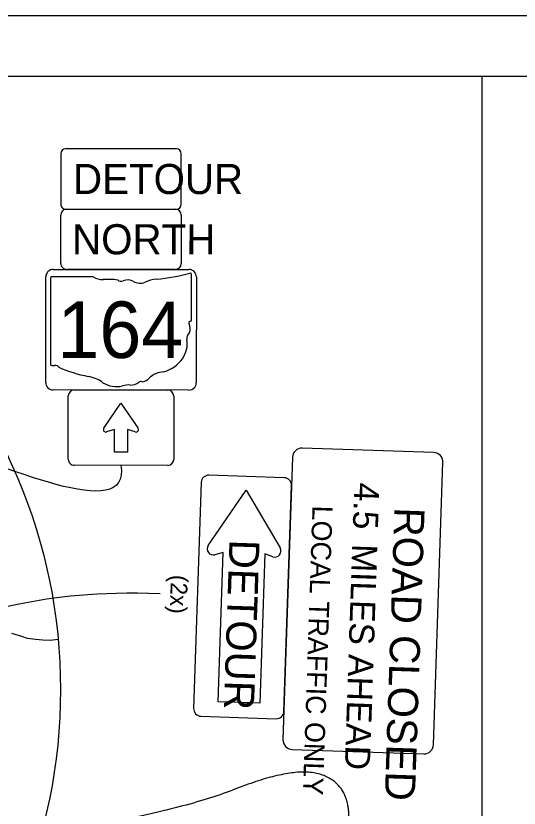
# Model space of a CAD drawing. Extents: x -202 to 1556, y 0 to 676.
# Drawn here: x 272.6 to 356.1, y 308.6 to 440 of the extents above; entities that cross this region are included whole.
import ezdxf

# ---------------------------------------------------------------- set-up
doc = ezdxf.new("R2010")
doc.units = 0
for name, color, linetype in [('Default', 7, 'Continuous'), ('GM_X_Minor_Lake', 7, 'Continuous'), ('GM_X_Minor_Lake_Text', 7, 'Continuous'), ('GM_X_Minor_River_Text', 7, 'Continuous'), ('SH_Border', 7, 'Continuous'), ('SH_Cut_Line', 7, 'Continuous'), ('SH_Data', 7, 'Continuous')]:
    doc.layers.add(name, color=color, linetype=linetype)

msp = doc.modelspace()

# ---------------------------------------------------------------- linework, layer by layer
at = {"layer": 'Default'}
msp.add_lwpolyline([(279.61, 336.58), (279.54, 336.57), (278.34, 336.4), (277.09, 336.41), (275.87, 336.52), (274.54, 336.72), (273.56, 337.02), (271.92, 337.55)], dxfattribs=at)
at = {"layer": 'GM_X_Minor_Lake'}
for p, q in [((281.05, 407.94), (299.05, 407.93)), ((280.05, 398.94), (280.05, 406.94)), ((300.05, 406.93), (300.05, 398.93)), ((299.05, 397.93), (281.05, 397.94)), ((301.76, 389.61), (301.77, 397.06)), ((278.33, 396.47), (278.32, 382.24)), ((285.42, 396.71), (278.56, 396.71)), ((301.76, 389.61), (301.76, 389.61)), ((282.29, 377.94), (297.79, 377.93)), ((281.29, 366.44), (281.29, 376.94)), ((298.79, 376.93), (298.79, 366.43)), ((287.2, 371.61), (290.04, 375.75)), ((290.04, 375.75), (292.84, 371.67)), ((288.95, 371.37), (287.66, 370.97)), ((288.94, 367.62), (288.95, 371.37)), ((292.42, 370.97), (291.13, 371.37)), ((291.13, 371.37), (291.13, 367.62)), ((291.13, 367.62), (288.94, 367.62)), ((297.79, 365.43), (282.29, 365.44)), ((304.52, 352.13), (310.81, 361.3)), ((310.81, 361.3), (316.46, 351.73)), ((307.02, 351), (305.62, 350.61)), ((306.19, 326.23), (307.02, 351)), ((313.89, 350.77), (313.06, 326)), ((315.26, 350.28), (313.89, 350.77)), ((313.06, 326), (306.19, 326.23))]:
    msp.add_line(p, q, dxfattribs=at)
for points in [[(280.05, 417.14), (280.05, 408.74)], [(299.25, 417.93), (280.85, 417.94)], [(300.05, 408.73), (300.05, 417.13)], [(280.85, 407.94), (299.25, 407.93)], [(278.8, 397.94), (301.3, 397.93)], [(277.54, 379.19), (277.55, 396.69)], [(302.55, 396.68), (302.54, 379.18)], [(301.29, 377.93), (278.79, 377.94)], [(317.13, 363.38), (304.64, 363.8)], [(303.35, 362.59), (302.09, 325.11)], [(317.08, 324.61), (318.34, 362.09)], [(303.3, 323.82), (315.79, 323.4)]]:
    msp.add_lwpolyline(points, dxfattribs=at)
for centre, radius, start, end in [((280.85, 417.14), 0.8, 89.9827, 179.9827), ((299.25, 417.13), 0.8, 359.9827, 89.9827), ((280.85, 408.74), 0.8, 179.9827, 269.9827), ((281.05, 406.94), 1, 89.9827, 179.9827), ((299.05, 406.93), 1, 359.9827, 89.9827), ((299.25, 408.73), 0.8, 269.9827, 359.9827), ((281.05, 398.94), 1, 179.9827, 269.9827), ((299.05, 398.93), 1, 269.9827, 359.9827), ((278.8, 396.69), 1.25, 89.9827, 179.9827), ((301.3, 396.68), 1.25, 359.9827, 89.9827), ((278.79, 379.19), 1.25, 179.9827, 269.9827), ((301.29, 379.18), 1.25, 269.9827, 359.9827), ((282.29, 376.94), 1, 89.9827, 179.9827), ((297.79, 376.93), 1, 359.9827, 89.9827), ((287.54, 371.37), 0.417, 145.3939, 287.1873), ((292.54, 371.37), 0.417, 252.7781, 44.9923), ((282.29, 366.44), 1, 179.9827, 269.9827), ((297.79, 366.43), 1, 269.9827, 359.9827), ((304.6, 362.55), 1.25, 88.0794, 178.0794), ((317.09, 362.13), 1.25, 358.0794, 88.0794), ((305.35, 351.57), 1, 145.5686, 285.8983), ((315.6, 351.22), 1, 250.2605, 30.5903), ((303.34, 325.07), 1.25, 178.0794, 268.0794), ((315.83, 324.65), 1.25, 268.0794, 358.0794)]:
    msp.add_arc(centre, radius, start, end, dxfattribs=at)
for centre, major_axis, start_param, end_param in [((293.42, 416.11), (24.85, -0.01), 4.814394, 5.042369), ((301.51, 397.09), (0.261, 0), 6.141152, 7.989035), ((278.6, 396.5), (0.272, 0), 1.712693, 3.28349), ((287.06, 398.36), (2.63, 0), 4.042523, 4.731795), ((287.93, 388.72), (9.45, 0), 1.404758, 1.657858), ((290.08, 396.57), (0.76, 0), 3.836095, 5.185415), ((291.19, 394.92), (1.58, 0), 0.950623, 2.079405), ((293.23, 397.18), (1.9, 0), 4.081561, 5.145723), ((296.59, 392.36), (5, 0), 1.699011, 2.107814), ((301.7, 389.07), (0.404, 0), 1.883978, 3.671073), ((301.49, 389.58), (0.279, 0), 5.05454, 6.418171), ((299.13, 388.13), (2.42, 0), 5.934695, 6.695948), ((302.7, 386.5), (1.76, 0), 2.387724, 3.262537), ((294.81, 385.55), (6.22, 0), 5.101752, 6.440018), ((278.6, 382.2), (0.274, 0), 3.00124, 4.508301), ((278.64, 383.66), (2.09, 0), 4.665946, 4.897461), ((279.06, 381.41), (0.754, 0), 0.519207, 1.627899), ((288.58, 394.2), (17.95, -0.01), 4.195997, 4.488961), ((283.23, 375.84), (5.62, 0), 0.823519, 1.323587), ((293.11, 380.85), (2.01, 0), 4.937069, 5.64225), ((297.43, 378.24), (3.4, 0), 1.647645, 2.488434), ((289.3, 381.34), (3.56, 0), 4.026481, 4.996735), ((291.36, 376.42), (2.93, 0), 1.495662, 1.94098), ((291.62, 380.27), (1.9, 0), 4.691044, 5.507374), ((293.34, 378.9), (0.535, 0), 1.147584, 2.315152)]:
    msp.add_ellipse(centre, major_axis=major_axis, ratio=0.8, start_param=start_param, end_param=end_param, dxfattribs=at)
at = {"layer": 'GM_X_Minor_Lake_Text'}
for points in [[(341.97, 367.55), (320.11, 368.28)], [(318.49, 366.77), (316.92, 319.93)], [(341.91, 319.09), (343.48, 365.94)], [(318.43, 318.31), (340.3, 317.58)]]:
    msp.add_lwpolyline(points, dxfattribs=at)
for centre, start, end in [((320.06, 366.72), 88.0794, 178.0794), ((341.92, 365.99), 358.0794, 88.0794), ((318.49, 319.87), 178.0794, 268.0794), ((340.35, 319.14), 268.0794, 358.0794)]:
    msp.add_arc(centre, 1.56, start, end, dxfattribs=at)
at = {"layer": 'GM_X_Minor_River_Text'}
msp.add_line((350, 10), (350, 430), dxfattribs=at)
at = {"layer": 'SH_Border'}
msp.add_lwpolyline([(30, 430), (670, 430), (670, 10), (30, 10)], close=True, dxfattribs=at)
at = {"layer": 'SH_Cut_Line'}
msp.add_lwpolyline([(0, 0), (680, 0), (680, 440), (0, 440)], close=True, dxfattribs=at)
at = {"layer": 'SH_Data'}
msp.add_circle((190, 328.22), 90, dxfattribs=at)
for points, degree in [([(290.04, 365.44), (291.68, 355.4), (249.47, 375.82), (233.91, 369.4), (203.27, 356.42), (192.62, 347.5)], 3), ([(296.55, 344.12), (275.7, 344.89), (260.18, 336.27), (208.96, 335.84), (193.5, 330.96), (191.48, 334.72)], 3), ([(296.55, 344.12), (275.7, 344.89), (260.18, 336.27), (208.96, 335.84), (194.18, 333.89), (191.66, 340.11)], 3), ([(327.87, 307.06), (327.87, 312.46), (319.07, 315.68), (299.39, 307.93), (261.96, 301.8), (211.63, 330.38), (195.44, 326.28), (192.62, 329.63)], 2), ([(281.76, 263.43), (274.75, 268.5), (283.53, 280.28), (254.72, 295.67), (211.15, 315.72), (198.85, 323.43)], 2)]:
    msp.add_open_spline(points, degree=degree, dxfattribs=at)

# ---------------------------------------------------------------- texts
at = {"layer": 'Default'}
msp.add_text('(2x)', height=2.8, rotation=268.0794, dxfattribs=at).set_placement((298.34, 347.3))
at = {"layer": 'GM_X_Minor_Lake'}
for s, height, rotation, p in [('DETOUR', 5, 359.9827, (282.08, 410.44)), ('NORTH', 5, 359.9827, (281.92, 400.44)), ('164', 9.375, 359.9827, (279.47, 383.24)), ('DETOUR', 5, 268.0794, (308.05, 353.17))]:
    msp.add_text(s, height=height, rotation=rotation, dxfattribs=at).set_placement(p)
at = {"layer": 'GM_X_Minor_Lake_Text'}
for s, height, p in [('4.5', 4.167, (328.78, 362.61)), ('LOCAL TRAFFIC ONLY', 3.3333, (321.84, 358.8)), ('ROAD CLOSED', 5, (335.45, 358.52)), ('MILES AHEAD', 4.1667, (328.43, 352.42))]:
    msp.add_text(s, height=height, rotation=268.0794, dxfattribs=at).set_placement(p)

doc.saveas('drawing.dxf')
